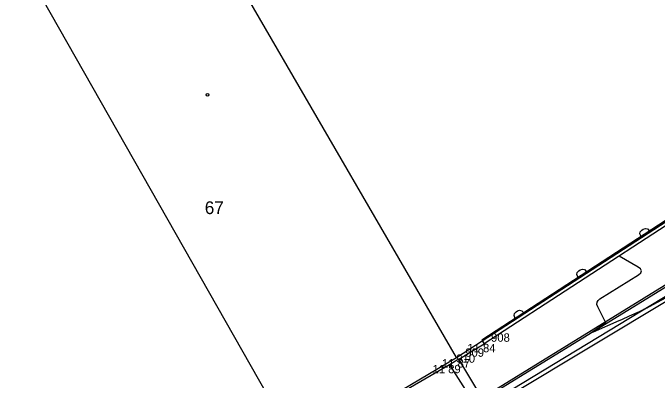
# Model space of a CAD drawing. Extents: x -703403 to -701924, y -1022520 to -1021856.
# Drawn here: x -703178.37 to -703156.9, y -1022090.98 to -1022078.73 of the extents above; entities that cross this region are included whole.
import ezdxf

# ---------------------------------------------------------------- set-up
doc = ezdxf.new("R2010")
doc.units = 0
for name, color, linetype in [('Ex_Minor Contours', 7, 'Continuous'), ('Z_body', 7, 'Continuous'), ('Z_body_cisla', 7, 'Continuous'), ('Z_body_vysky_redukovane', 7, 'Continuous'), ('Z_budova', 7, 'Continuous'), ('Z_katastr_cisla_stavebni', 7, 'Continuous'), ('Z_katastr_hranice', 7, 'Continuous'), ('Z_katastr_vnitrni_kresba', 7, 'Continuous'), ('Z_katastr_znacky_budov', 7, 'Continuous'), ('Z_komunikace', 7, 'Continuous'), ('Z_obruba', 7, 'Continuous'), ('Z_ploty', 7, 'Continuous'), ('Z_ploty_znacky', 7, 'Continuous'), ('Z_vstupy', 7, 'Continuous'), ('Z_zlabek', 7, 'Continuous')]:
    doc.layers.add(name, color=color, linetype=linetype)

# ---------------------------------------------------------------- blocks, each defined once
blk = doc.blocks.new('POINT_DISPLAY')
blk.add_line((0, 0), (0, 0))
blk = doc.blocks.new('Z216')
for p, q in [((-0.17, 0), (-0.15, 0.1)), ((-0.15, 0.1), (-0.1, 0.15)), ((-0.1, 0.15), (-0.03, 0.17)), ((-0.03, 0.17), (0.03, 0.17)), ((0.03, 0.17), (0.1, 0.15)), ((0.1, 0.15), (0.15, 0.1)), ((0.15, 0.1), (0.17, 0))]:
    blk.add_line(p, q)

msp = doc.modelspace()

# ---------------------------------------------------------------- linework, layer by layer
at = {"layer": 'Ex_Minor Contours'}
msp.add_lwpolyline([(-703155.128, -1022087.431), (-703157.158, -1022088.531), (-703157.24, -1022088.574), (-703157.323, -1022088.617), (-703157.406, -1022088.657), (-703157.49, -1022088.696), (-703157.829, -1022088.85), (-703157.914, -1022088.888), (-703157.999, -1022088.926), (-703158.084, -1022088.964), (-703158.169, -1022089.002), (-703159.025, -1022089.38), (-703159.086, -1022089.404), (-703159.109, -1022089.408), (-703159.093, -1022089.391), (-703159.04, -1022089.353), (-703158.613, -1022089.068), (-703158.61, -1022089.065), (-703158.608, -1022089.062), (-703158.608, -1022089.059), (-703158.609, -1022089.055), (-703158.626, -1022089.022), (-703158.875, -1022088.531), (-703158.903, -1022088.452), (-703158.899, -1022088.382), (-703158.866, -1022088.32), (-703158.802, -1022088.266), (-703157.52, -1022087.463), (-703157.442, -1022087.398), (-703157.417, -1022087.334), (-703157.445, -1022087.272), (-703157.524, -1022087.21), (-703158.16, -1022086.842)], dxfattribs=at)
at = {"layer": 'Z_budova'}
for p, q in [((-703163.51, -1022090.28), (-703163.82, -1022090.47)), ((-703163.82, -1022090.47), (-703168.82, -1022093.36))]:
    msp.add_line(p, q, dxfattribs=at)
at = {"layer": 'Z_katastr_hranice'}
for p, q in [((-703178.37, -1022076.52), (-703168.84, -1022093.32)), ((-703163.58, -1022090.23), (-703152.11, -1022082.77)), ((-703168.84, -1022093.32), (-703163.58, -1022090.23))]:
    msp.add_line(p, q, dxfattribs=at)
at = {"layer": 'Z_katastr_vnitrni_kresba'}
msp.add_line((-703163.58, -1022090.23), (-703173.22, -1022073.6), dxfattribs=at)
at = {"layer": 'Z_katastr_znacky_budov'}
msp.add_circle((-703171.882, -1022081.46), 0.0437, dxfattribs=at)
at = {"layer": 'Z_komunikace'}
msp.add_line((-703154.98, -1022087.38), (-703163.14, -1022092.29), dxfattribs=at)
at = {"layer": 'Z_obruba'}
for p, q in [((-703162.73, -1022091.56), (-703155.26, -1022086.96)), ((-703155.06, -1022087.25), (-703163.2, -1022092.18))]:
    msp.add_line(p, q, dxfattribs=at)
at = {"layer": 'Z_ploty'}
for p, q in [((-703156.25, -1022085.41), (-703162.74, -1022089.65)), ((-703156.16, -1022085.54), (-703162.66, -1022089.77)), ((-703162.74, -1022089.65), (-703162.66, -1022089.77))]:
    msp.add_line(p, q, dxfattribs=at)
at = {"layer": 'Z_vstupy'}
msp.add_line((-703163.51, -1022090.28), (-703162.66, -1022089.77), dxfattribs=at)
at = {"layer": 'Z_zlabek'}
for p, q in [((-703162.7, -1022091.61), (-703155.23, -1022087.02)), ((-703162.73, -1022091.56), (-703163.51, -1022090.28)), ((-703163.82, -1022090.47), (-703163.02, -1022091.72))]:
    msp.add_line(p, q, dxfattribs=at)

# ---------------------------------------------------------------- block references
at = {"layer": 'Z_body'}
for p in [(-703162.66, -1022089.77), (-703163.51, -1022090.28), (-703163.82, -1022090.47)]:
    msp.add_blockref('POINT_DISPLAY', p, dxfattribs=at)
at = {"layer": 'Z_ploty_znacky', "rotation": 33.1}
for p in [(-703157.29, -1022086.1), (-703159.39, -1022087.46), (-703161.48, -1022088.83)]:
    msp.add_blockref('Z216', p, dxfattribs=at)

# ---------------------------------------------------------------- texts
at = {"layer": 'Z_body_cisla'}
for s, p in [('908', (-703162.43, -1022089.7)), ('909', (-703163.29, -1022090.2)), ('910', (-703163.59, -1022090.4))]:
    msp.add_text(s, height=0.28, dxfattribs=at).set_placement(p)
at = {"layer": 'Z_body_vysky_redukovane'}
for s, p in [('11 84', (-703163.22, -1022090.05)), ('11 87', (-703164.07, -1022090.56)), ('11 89', (-703164.38, -1022090.75))]:
    msp.add_text(s, height=0.28, dxfattribs=at).set_placement(p)
at = {"layer": 'Z_katastr_cisla_stavebni'}
msp.add_text('67', height=0.425, dxfattribs=at).set_placement((-703171.973, -1022085.44))

doc.saveas('drawing.dxf')
